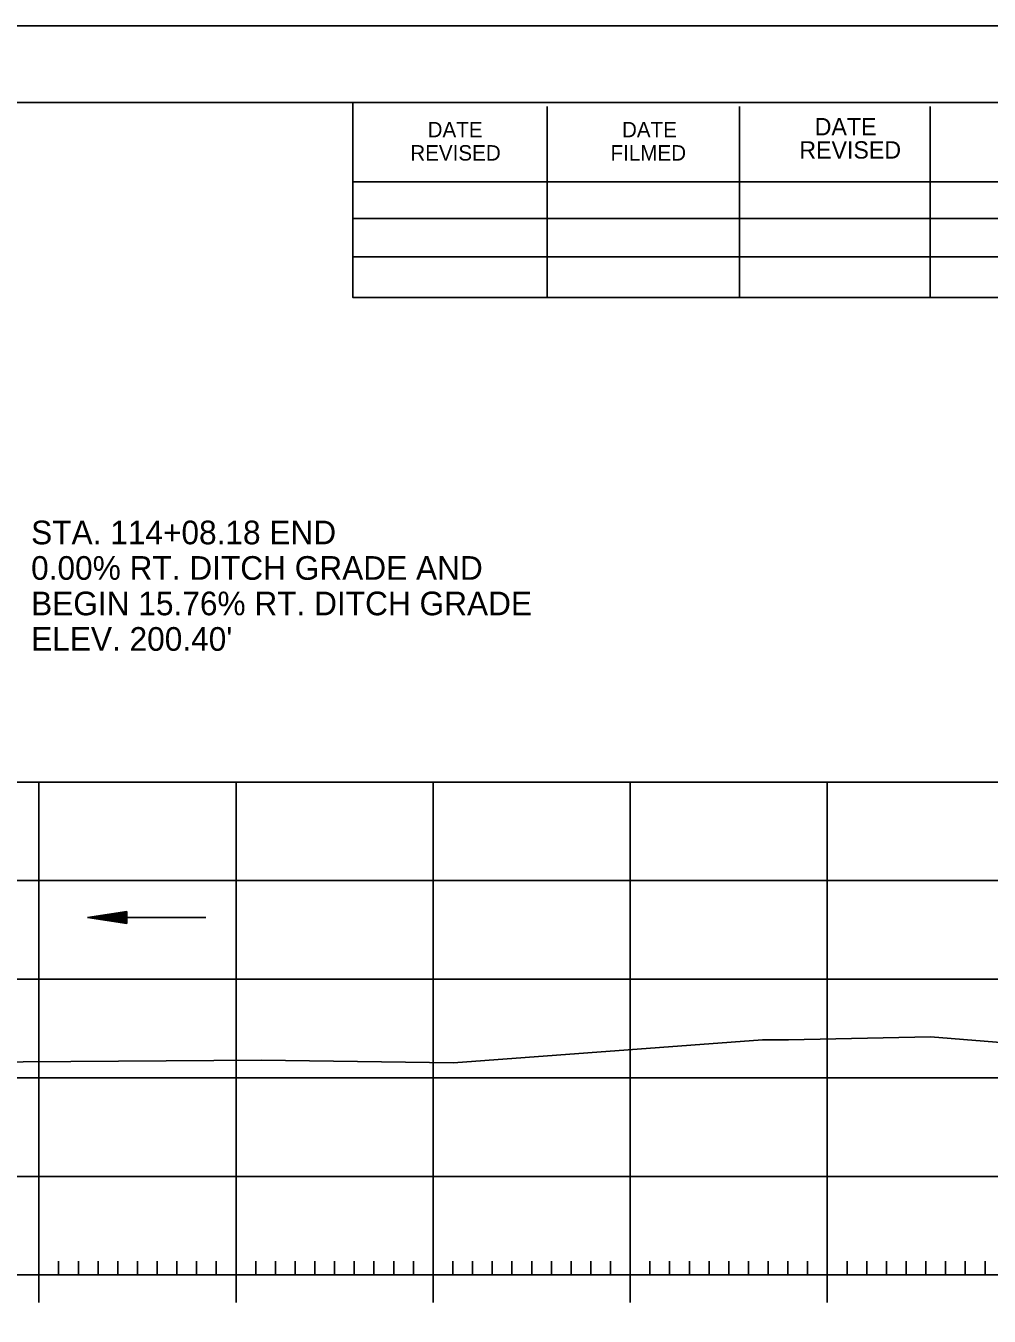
# Model space of a CAD drawing. Extents: x 1312042 to 1371461, y 379929 to 1834241.
# Drawn here: x 1371357.6 to 1371406.5, y 380076.8 to 380142.3 of the extents above; entities that cross this region are included whole.
import ezdxf

# ---------------------------------------------------------------- set-up
doc = ezdxf.new("R2010")
doc.units = 0
for name, color, linetype in [('R_Axis', 7, 'Continuous'), ('R_Border', 7, 'Continuous'), ('R_Drive', 7, 'Continuous'), ('R_Exist Surface', 7, 'Continuous'), ('R_Grid', 7, 'Continuous'), ('R_No Plot', 7, 'Continuous'), ('R_Water Annot', 7, 'Continuous')]:
    doc.layers.add(name, color=color, linetype=linetype)

msp = doc.modelspace()

# ---------------------------------------------------------------- linework, layer by layer
at = {"layer": 'R_Axis'}
for p, q in [((1371358.277, 380077.509), (1371358.277, 380080.309)), ((1371368.277, 380077.509), (1371368.277, 380080.309)), ((1371378.277, 380077.509), (1371378.277, 380080.309)), ((1371388.277, 380077.509), (1371388.277, 380080.309)), ((1371398.277, 380077.509), (1371398.277, 380080.309)), ((1371359.277, 380078.909), (1371359.277, 380079.609)), ((1371360.277, 380078.909), (1371360.277, 380079.609)), ((1371361.277, 380078.909), (1371361.277, 380079.609)), ((1371362.277, 380078.909), (1371362.277, 380079.609)), ((1371363.277, 380078.909), (1371363.277, 380079.609)), ((1371364.277, 380078.909), (1371364.277, 380079.609)), ((1371365.277, 380078.909), (1371365.277, 380079.609)), ((1371366.277, 380078.909), (1371366.277, 380079.609)), ((1371367.277, 380078.909), (1371367.277, 380079.609)), ((1371369.277, 380078.909), (1371369.277, 380079.609)), ((1371370.277, 380078.909), (1371370.277, 380079.609)), ((1371371.277, 380078.909), (1371371.277, 380079.609)), ((1371372.277, 380078.909), (1371372.277, 380079.609)), ((1371373.277, 380078.909), (1371373.277, 380079.609)), ((1371374.277, 380078.909), (1371374.277, 380079.609)), ((1371375.277, 380078.909), (1371375.277, 380079.609)), ((1371376.277, 380078.909), (1371376.277, 380079.609)), ((1371377.277, 380078.909), (1371377.277, 380079.609)), ((1371379.277, 380078.909), (1371379.277, 380079.609)), ((1371380.277, 380078.909), (1371380.277, 380079.609)), ((1371381.277, 380078.909), (1371381.277, 380079.609)), ((1371382.277, 380078.909), (1371382.277, 380079.609)), ((1371383.277, 380078.909), (1371383.277, 380079.609)), ((1371384.277, 380078.909), (1371384.277, 380079.609)), ((1371385.277, 380078.909), (1371385.277, 380079.609)), ((1371386.277, 380078.909), (1371386.277, 380079.609)), ((1371387.277, 380078.909), (1371387.277, 380079.609)), ((1371389.277, 380078.909), (1371389.277, 380079.609)), ((1371390.277, 380078.909), (1371390.277, 380079.609)), ((1371391.277, 380078.909), (1371391.277, 380079.609)), ((1371392.277, 380078.909), (1371392.277, 380079.609)), ((1371393.277, 380078.909), (1371393.277, 380079.609)), ((1371394.277, 380078.909), (1371394.277, 380079.609)), ((1371395.277, 380078.909), (1371395.277, 380079.609)), ((1371396.277, 380078.909), (1371396.277, 380079.609)), ((1371397.277, 380078.909), (1371397.277, 380079.609)), ((1371399.277, 380078.909), (1371399.277, 380079.609)), ((1371400.277, 380078.909), (1371400.277, 380079.609)), ((1371401.277, 380078.909), (1371401.277, 380079.609)), ((1371402.277, 380078.909), (1371402.277, 380079.609)), ((1371403.277, 380078.909), (1371403.277, 380079.609)), ((1371404.277, 380078.909), (1371404.277, 380079.609)), ((1371405.277, 380078.909), (1371405.277, 380079.609)), ((1371406.277, 380078.909), (1371406.277, 380079.609)), ((1371158.277, 380078.909), (1371438.277, 380078.909))]:
    msp.add_line(p, q, dxfattribs=at)
at = {"layer": 'R_Border'}
for p, q in [((1371140.277, 380138.369), (1371456.457, 380138.369)), ((1371374.197, 380128.489), (1371374.197, 380138.369)), ((1371384.057, 380128.489), (1371384.057, 380138.169)), ((1371393.817, 380128.489), (1371393.817, 380138.169)), ((1371403.497, 380128.489), (1371403.497, 380138.169)), ((1371374.197, 380134.349), (1371413.357, 380134.349)), ((1371374.197, 380132.489), (1371413.357, 380132.489)), ((1371374.197, 380128.489), (1371374.197, 380130.549)), ((1371374.197, 380130.549), (1371413.357, 380130.549)), ((1371456.457, 380128.489), (1371374.197, 380128.489))]:
    msp.add_line(p, q, dxfattribs=at)
at = {"layer": 'R_Exist Surface'}
msp.add_lwpolyline([(1371352.617, 380089.688), (1371369.575, 380089.81), (1371379.307, 380089.668), (1371394.991, 380090.832), (1371396.306, 380090.839), (1371403.519, 380090.982), (1371419.223, 380089.723), (1371426.924, 380090.582), (1371429.352, 380090.807), (1371433.568, 380091.216), (1371438.277, 380091.459)], dxfattribs=at)
at = {"layer": 'R_Grid'}
for p, q in [((1371158.277, 380103.909), (1371438.277, 380103.909)), ((1371358.277, 380078.909), (1371358.277, 380103.909)), ((1371368.277, 380078.909), (1371368.277, 380103.909)), ((1371378.277, 380078.909), (1371378.277, 380103.909)), ((1371388.277, 380078.909), (1371388.277, 380103.909)), ((1371398.277, 380078.909), (1371398.277, 380103.909)), ((1371158.277, 380098.909), (1371438.277, 380098.909)), ((1371158.277, 380093.909), (1371438.277, 380093.909)), ((1371158.277, 380088.909), (1371438.277, 380088.909)), ((1371158.277, 380083.909), (1371438.277, 380083.909)), ((1371158.277, 380078.909), (1371438.277, 380078.909))]:
    msp.add_line(p, q, dxfattribs=at)
at = {"layer": 'R_No Plot'}
msp.add_line((1371127.876, 380142.263), (1371461.209, 380142.263), dxfattribs=at)
for points in [[(1371127.869, 380142.263), (1371461.209, 380142.263), (1371461.209, 379928.926), (1371127.869, 379928.926)], [(1371374.197, 380138.369), (1371374.197, 380128.489), (1371409.929, 380128.489), (1371409.929, 380125.569), (1371433.128, 380125.569), (1371433.128, 380101.236), (1371456.457, 380101.236), (1371456.457, 379932.909), (1371140.277, 379932.909), (1371140.277, 380138.369)]]:
    msp.add_lwpolyline(points, close=True, dxfattribs=at)
at = {"layer": 'R_Water Annot'}
for p, q in [((1371362.738, 380097.337), (1371360.738, 380097.037)), ((1371366.738, 380097.037), (1371360.738, 380097.037)), ((1371362.738, 380096.737), (1371360.738, 380097.037)), ((1371362.738, 380097.287), (1371361.072, 380097.037)), ((1371362.738, 380096.787), (1371361.072, 380097.037)), ((1371362.738, 380097.236), (1371361.416, 380097.037)), ((1371362.738, 380096.838), (1371361.416, 380097.037)), ((1371362.738, 380097.186), (1371361.749, 380097.037)), ((1371362.738, 380096.888), (1371361.749, 380097.037)), ((1371362.738, 380097.135), (1371362.088, 380097.037)), ((1371362.738, 380096.94), (1371362.088, 380097.037)), ((1371362.738, 380097.084), (1371362.422, 380097.037)), ((1371362.738, 380096.99), (1371362.422, 380097.037)), ((1371362.738, 380096.737), (1371362.738, 380097.337))]:
    msp.add_line(p, q, dxfattribs=at)

# ---------------------------------------------------------------- texts
at = {"layer": 'R_Border'}
for s, height, p in [('DATE', 0.7819, (1371377.997, 380136.609)), ('DATE', 0.7819, (1371387.857, 380136.609)), ('DATE', 0.8792, (1371397.637, 380136.709)), ('REVISED', 0.7819, (1371377.117, 380135.429)), ('FILMED', 0.7819, (1371387.277, 380135.429)), ('REVISED', 0.8792, (1371396.857, 380135.529))]:
    msp.add_text(s, height=height, rotation=360, dxfattribs=at).set_placement(p)
at = {"layer": 'R_Drive'}
for s, p in [('STA. 114+08.18 END', (1371357.881, 380115.967)), ('0.00% RT. DITCH GRADE AND', (1371357.881, 380114.167)), ('BEGIN 15.76% RT. DITCH GRADE', (1371357.881, 380112.367)), ("ELEV. 200.40'", (1371357.881, 380110.567))]:
    msp.add_text(s, height=1.2, dxfattribs=at).set_placement(p)

doc.saveas('drawing.dxf')
